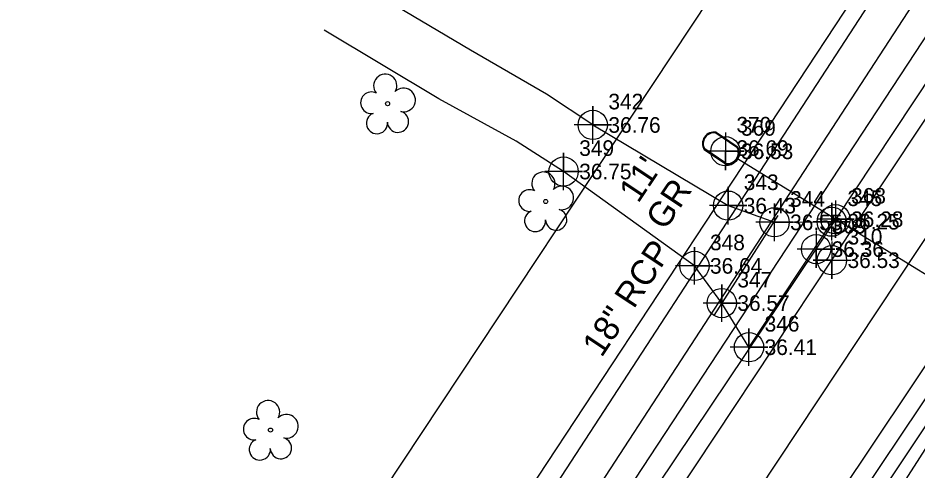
# Model space of a CAD drawing. Extents: x 2603627 to 2605187, y 896619 to 899063.
# Drawn here: x 2604617.7 to 2604761.6, y 898454.7 to 898527.2 of the extents above; entities that cross this region are included whole.
import ezdxf

# ---------------------------------------------------------------- set-up
doc = ezdxf.new("R2010")
doc.units = 0
for name, color, linetype in [('Exist Horizontal Alignment', 7, 'Continuous'), ('Exist Right of Way Line', 7, 'Continuous'), ('Exist Roads EOP', 7, 'Continuous'), ('Exist Roads EOP Cogo Elevation', 7, 'Continuous'), ('Exist Roads EOP Cogo Number', 7, 'Continuous'), ('Exist Roads EOP Cogo Point CELL', 7, 'Continuous'), ('Exist Roads EOT', 7, 'Continuous'), ('Exist Roads EOT Cogo Elevation', 7, 'Continuous'), ('Exist Roads EOT Cogo Number', 7, 'Continuous'), ('Exist Roads EOT Cogo Point CELL', 7, 'Continuous'), ('Exist Roads Soil', 7, 'Continuous'), ('Exist Roads Soil Cogo Elevation', 7, 'Continuous'), ('Exist Roads Soil Cogo Number', 7, 'Continuous'), ('Exist Roads Soil Cogo Point CELL', 7, 'Continuous'), ('Exist Roads Soil Text', 7, 'Continuous'), ('Exist Structure Minor Pipes RCP 18 Inch', 7, 'Continuous'), ('Exist Structure Minor Pipes RCP 18 Inch Text', 7, 'Continuous'), ('Exist Utilities Telephone UG Cable SUE LOS C', 7, 'Continuous'), ('Exist Utilities Telephone UG FO SUE LOS C', 7, 'Continuous'), ('Exist Utilities Water Meter CELL', 7, 'Continuous'), ('Exist Utilities Water Meter Cogo Elevation', 7, 'Continuous'), ('Exist Utilities Water Meter Cogo Number', 7, 'Continuous'), ('Exist Utilities Water UG Line SUE LOS B', 7, 'Continuous'), ('Exist Utilities Water UG Line SUE LOS B Cogo Elevation', 7, 'Continuous'), ('Exist Utilities Water UG Line SUE LOS B Cogo Number', 7, 'Continuous'), ('Exist Utilities Water UG Line SUE LOS B Cogo Point CELL', 7, 'Continuous'), ('Exist Vegetation Tree CELL', 7, 'Continuous')]:
    doc.layers.add(name, color=color, linetype=linetype)

# ---------------------------------------------------------------- blocks, each defined once
blk = doc.blocks.new('EXIST ROADS EOP COGO POINT')
at = {"layer": 'Exist Roads EOP Cogo Point CELL'}
blk.add_lwpolyline([(0, 0.06), (0, -0.06), (0, 0), (0.06, 0), (-0.06, 0)], dxfattribs=at)
blk.add_circle((0, 0), 0.0469, dxfattribs=at)
blk = doc.blocks.new('EXIST ROADS EOT COGO POINT')
at = {"layer": 'Exist Roads EOT Cogo Point CELL'}
blk.add_lwpolyline([(0, 0.06), (0, -0.06), (0, 0), (-0.06, 0), (0.06, 0)], dxfattribs=at)
blk.add_circle((0, 0), 0.0469, dxfattribs=at)
blk = doc.blocks.new('EXIST ROADS SOIL COGO POINT')
at = {"layer": 'Exist Roads Soil Cogo Point CELL'}
blk.add_lwpolyline([(0, -0.06), (0, 0.06), (0, 0), (0.06, 0), (-0.06, 0)], dxfattribs=at)
blk.add_circle((0, 0), 0.0469, dxfattribs=at)
blk = doc.blocks.new('EXIST UTILITIES WATER UG LINE SUE LOS B COGO POINT')
at = {"layer": 'Exist Utilities Water UG Line SUE LOS B Cogo Point CELL'}
blk.add_lwpolyline([(0, 0.06), (0, -0.06), (0, 0), (0.06, 0), (-0.06, 0)], dxfattribs=at)
blk.add_circle((0, 0), 0.0469, dxfattribs=at)
blk = doc.blocks.new('EXIST UTILITIES WATER METER')
at = {"layer": 'Exist Utilities Water Meter CELL'}
blk.add_line((0, 0), (0, 0), dxfattribs=at)
for points in [[(-0.0408, 0.034), (0.0408, 0.034)], [(-0.0408, 0.0312), (0.0408, 0.0312)], [(0.0408, -0.0312), (-0.0413, -0.0312)], [(0.0408, -0.034), (-0.0413, -0.034)]]:
    blk.add_lwpolyline(points, dxfattribs=at)
for centre, radius, start, end in [((-0.0261, -0.0001), 0.0371, 113.178, 245.9794), ((-0.0259, -0.0001), 0.0347, 115.3009, 243.7824), ((0.0259, 0), 0.0371, 293.6483, 66.3084), ((0.0261, 0), 0.0345, 295.1272, 64.8728)]:
    blk.add_arc(centre, radius, start, end, dxfattribs=at)

msp = doc.modelspace()

# ---------------------------------------------------------------- linework, layer by layer
at = {"layer": 'Exist Horizontal Alignment'}
msp.add_line((2604681.44, 898368.79), (2605041.11, 898911.74), dxfattribs=at)
at = {"layer": 'Exist Right of Way Line'}
msp.add_line((2604639.76, 898396.41), (2604999.42, 898939.36), dxfattribs=at)
at = {"layer": 'Exist Roads EOP'}
for points in [[(2604577.96, 898237.27), (2604606.45, 898281.24), (2604633.89, 898322.5), (2604662.45, 898365.47), (2604690.62, 898408.06), (2604717.29, 898448.09), (2604745.46, 898490.11), (2604773.6, 898532.6), (2604800.88, 898573.95), (2604828.34, 898615.46), (2604855.1, 898656.15), (2604883.53, 898699.09), (2604911.29, 898740.95), (2604939.38, 898783.41), (2604966.33, 898824.04), (2604993.38, 898865.27), (2605022.2, 898908.38), (2605029.46, 898919.46)], [(2604713.86, 898392.44), (2604740.28, 898432.25), (2604768.45, 898474.26), (2604797.27, 898517.92), (2604823.93, 898558.47), (2604851.31, 898599.84), (2604878.52, 898641.09), (2604906.84, 898683.65), (2604934.68, 898725.71), (2604962.63, 898767.92), (2604989.32, 898808.49), (2605016.42, 898849.59), (2605045.34, 898893.33), (2605052.55, 898904.16)]]:
    msp.add_lwpolyline(points, dxfattribs=at)
at = {"layer": 'Exist Roads EOT'}
for points in [[(2604580.65, 898235.67), (2604609.23, 898279.3), (2604636.66, 898320.72), (2604665.18, 898363.91), (2604693.37, 898406.36), (2604719.95, 898446.05), (2604748, 898488.34), (2604776.15, 898530.84), (2604803.5, 898572.3), (2604830.95, 898613.91), (2604857.58, 898654.47), (2604886.02, 898697.38), (2604913.86, 898739.33), (2604942.03, 898781.72), (2604969.06, 898822.38), (2604996.07, 898863.44), (2605024.73, 898906.73), (2605032, 898917.78)], [(2604598.04, 898223.4), (2604627.23, 898267.23), (2604654.64, 898308.57), (2604683.28, 898352.01), (2604711.27, 898394.14), (2604737.98, 898434.05), (2604766.04, 898475.94), (2604794.96, 898519.26), (2604821.61, 898559.82), (2604848.89, 898601.4), (2604876.12, 898642.73), (2604904.4, 898685.35), (2604932.33, 898727.23), (2604960.29, 898769.49), (2604987.32, 898810.19), (2605014.12, 898850.95), (2605043.08, 898894.89), (2605050.2, 898905.72)]]:
    msp.add_lwpolyline(points, dxfattribs=at)
at = {"layer": 'Exist Roads Soil'}
for p, q in [((2604709.71, 898510.01), (2604702.3, 898514.93)), ((2604705.04, 898502.55), (2604697.44, 898507.43))]:
    msp.add_line(p, q, dxfattribs=at)
for points in [[(2604702.3, 898514.93), (2604690.11, 898521.97), (2604671.82, 898532.91)], [(2604697.44, 898507.43), (2604685.07, 898514.22), (2604666.71, 898525.2)], [(2604709.71, 898510.01), (2604731.38, 898497.08), (2604738.81, 898494.41), (2604747.98, 898494.51), (2604734.72, 898474.4), (2604730.36, 898481.47), (2604725.98, 898487.43), (2604705.04, 898502.55)]]:
    msp.add_lwpolyline(points, dxfattribs=at)
at = {"layer": 'Exist Structure Minor Pipes RCP 18 Inch'}
msp.add_line((2604729.12, 898479.5), (2604739.41, 898495.51), dxfattribs=at)
at = {"layer": 'Exist Utilities Telephone UG Cable SUE LOS C'}
for p, q in [((2604658.71, 898389.49), (2604852.96, 898684.66)), ((2604753.32, 898447.21), (2604850.74, 898593.69)), ((2604580.04, 898245.37), (2604795.48, 898573.63))]:
    msp.add_line(p, q, dxfattribs=at)
at = {"layer": 'Exist Utilities Telephone UG FO SUE LOS C'}
for p, q in [((2604671.2, 898402.26), (2605014.35, 898929.48)), ((2604676.14, 898398.98), (2605019.3, 898926.2))]:
    msp.add_line(p, q, dxfattribs=at)
at = {"layer": 'Exist Utilities Water UG Line SUE LOS B'}
for points in [[(2604590.41, 898183.07), (2604608.13, 898210.78), (2604631.33, 898247.72), (2604631.98, 898248.77), (2604637.93, 898260.9), (2604650.01, 898281.75), (2604670.13, 898312.66), (2604706.14, 898370.49), (2604744.2, 898428.79), (2604775.85, 898478.14), (2604817.62, 898541.22), (2604844.76, 898580.18), (2604876.2, 898627.22), (2604907.55, 898675.15), (2604931.69, 898711.47), (2604963.51, 898758.63), (2604991.08, 898800.9), (2605022.23, 898847.26), (2605044.13, 898880.13), (2605057.71, 898900.74)], [(2604775.86, 898478.17), (2604748.57, 898494.9), (2604732.86, 898504.6)]]:
    msp.add_lwpolyline(points, dxfattribs=at)
at = {"layer": 'Exist Vegetation Tree CELL'}
for p, q in [((2604676.86, 898513.42), (2604676.86, 898513.42)), ((2604702.18, 898497.75), (2604702.18, 898497.75)), ((2604658.11, 898461.12), (2604658.11, 898461.12))]:
    msp.add_line(p, q, dxfattribs=at)
for centre in [(2604676.86, 898513.42), (2604702.18, 898497.75), (2604658.11, 898461.12)]:
    msp.add_circle(centre, 0.326, dxfattribs=at)
for centre, radius, start, end in [((2604676.48, 898516.29), 1.86, 330.1651, 219.7134), ((2604679.41, 898514), 1.9, 257.1011, 134.1999), ((2604674.26, 898513.57), 1.73, 62.6636, 279.3457), ((2604675.16, 898510.29), 1.69, 111.5671, 6.231), ((2604678.53, 898510.52), 1.7, 181.2822, 74.56), ((2604701.8, 898500.62), 1.86, 330.1651, 219.7134), ((2604704.73, 898498.33), 1.9, 257.1011, 134.1999), ((2604699.58, 898497.9), 1.73, 62.6636, 279.3457), ((2604700.48, 898494.62), 1.69, 111.5671, 6.231), ((2604703.86, 898494.85), 1.7, 181.2822, 74.56), ((2604657.72, 898463.99), 1.86, 330.1651, 219.7134), ((2604655.5, 898461.27), 1.73, 62.6636, 279.3457), ((2604660.66, 898461.71), 1.9, 257.1011, 134.1999), ((2604659.78, 898458.22), 1.7, 181.2822, 74.56), ((2604656.4, 898458), 1.69, 111.5671, 6.231)]:
    msp.add_arc(centre, radius, start, end, dxfattribs=at)

# ---------------------------------------------------------------- block references
at = {"layer": 'Exist Roads EOP Cogo Point CELL', "xscale": 50, "yscale": 50}
msp.add_blockref('EXIST ROADS EOP COGO POINT', (2604745.46, 898490.11), dxfattribs=at)
at = {"layer": 'Exist Roads EOT Cogo Point CELL', "xscale": 50, "yscale": 50}
msp.add_blockref('EXIST ROADS EOT COGO POINT', (2604748, 898488.34), dxfattribs=at)
at = {"layer": 'Exist Roads Soil Cogo Point CELL', "xscale": 50, "yscale": 50}
for p in [(2604709.71, 898510.01), (2604705.04, 898502.55), (2604731.38, 898497.08), (2604738.81, 898494.41), (2604747.98, 898494.51), (2604725.98, 898487.43), (2604730.36, 898481.47), (2604734.72, 898474.4)]:
    msp.add_blockref('EXIST ROADS SOIL COGO POINT', p, dxfattribs=at)
at = {"layer": 'Exist Utilities Water Meter CELL', "xscale": 50, "yscale": 50, "rotation": -33.955010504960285}
msp.add_blockref('EXIST UTILITIES WATER METER', (2604730.21, 898506.3), dxfattribs=at)
at = {"layer": 'Exist Utilities Water UG Line SUE LOS B Cogo Point CELL', "xscale": 50, "yscale": 50}
for p in [(2604730.94, 898505.79), (2604748.57, 898494.9)]:
    msp.add_blockref('EXIST UTILITIES WATER UG LINE SUE LOS B COGO POINT', p, dxfattribs=at)

# ---------------------------------------------------------------- texts
at = {"layer": 'Exist Roads EOP Cogo Elevation'}
msp.add_text('36.36', height=2.5, dxfattribs=at).set_placement((2604747.96, 898488.86))
at = {"layer": 'Exist Roads EOP Cogo Number'}
msp.add_text('309', height=2.5, dxfattribs=at).set_placement((2604747.96, 898492.61))
at = {"layer": 'Exist Roads EOT Cogo Elevation'}
msp.add_text('36.53', height=2.5, dxfattribs=at).set_placement((2604750.5, 898487.09))
at = {"layer": 'Exist Roads EOT Cogo Number'}
msp.add_text('310', height=2.5, dxfattribs=at).set_placement((2604750.5, 898490.84))
at = {"layer": 'Exist Roads Soil Cogo Elevation'}
for s, p in [('36.76', (2604712.21, 898508.76)), ('36.75', (2604707.54, 898501.3)), ('36.43', (2604733.88, 898495.83)), ('36.55', (2604741.31, 898493.16)), ('36.25', (2604750.48, 898493.26)), ('36.64', (2604728.48, 898486.18)), ('36.57', (2604732.86, 898480.22)), ('36.41', (2604737.22, 898473.15))]:
    msp.add_text(s, height=2.5, dxfattribs=at).set_placement(p)
at = {"layer": 'Exist Roads Soil Cogo Number'}
for s, p in [('342', (2604712.21, 898512.51)), ('349', (2604707.54, 898505.05)), ('343', (2604733.88, 898499.58)), ('344', (2604741.31, 898496.91)), ('345', (2604750.48, 898497.01)), ('348', (2604728.48, 898489.93)), ('347', (2604732.86, 898483.97)), ('346', (2604737.22, 898476.9))]:
    msp.add_text(s, height=2.5, dxfattribs=at).set_placement(p)
at = {"layer": 'Exist Roads Soil Text'}
for s, p in [("11' ", (2604716.98, 898497.33)), ('GR', (2604721.28, 898492.95))]:
    msp.add_text(s, height=4, rotation=56.3361, dxfattribs=at).set_placement(p)
at = {"layer": 'Exist Structure Minor Pipes RCP 18 Inch Text'}
msp.add_text('18" RCP', height=4, rotation=56.4786, dxfattribs=at).set_placement((2604711.12, 898472.62))
at = {"layer": 'Exist Utilities Water Meter Cogo Elevation'}
msp.add_text('36.69', height=2.5, dxfattribs=at).set_placement((2604732.71, 898505.05))
at = {"layer": 'Exist Utilities Water Meter Cogo Number'}
msp.add_text('370', height=2.5, dxfattribs=at).set_placement((2604732.71, 898508.8))
at = {"layer": 'Exist Utilities Water UG Line SUE LOS B Cogo Elevation'}
for s, p in [('36.53', (2604733.44, 898504.54)), ('36.28', (2604751.07, 898493.65))]:
    msp.add_text(s, height=2.5, dxfattribs=at).set_placement(p)
at = {"layer": 'Exist Utilities Water UG Line SUE LOS B Cogo Number'}
for s, p in [('369', (2604733.44, 898508.29)), ('368', (2604751.07, 898497.4))]:
    msp.add_text(s, height=2.5, dxfattribs=at).set_placement(p)

doc.saveas('drawing.dxf')
